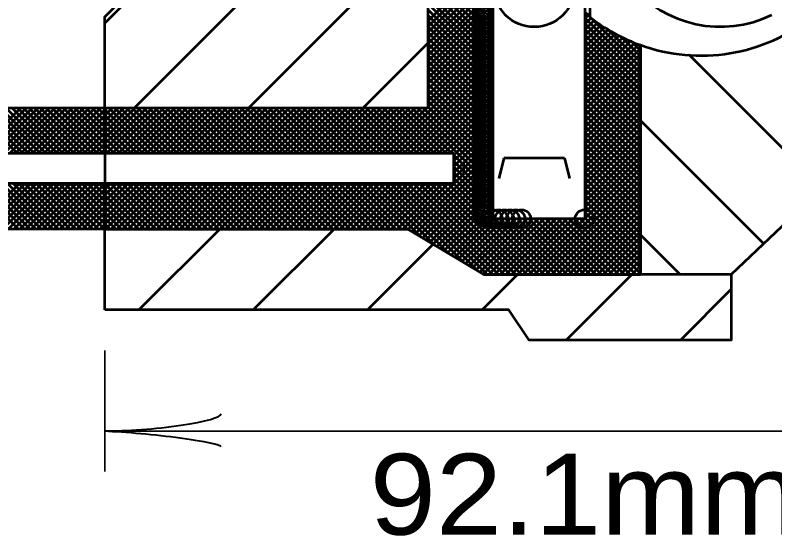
# Model space of a CAD drawing. Extents: x -32 to 824, y -6 to 538.
# Drawn here: x 144.51 to 167.06, y 179.61 to 195.06 of the extents above; entities that cross this region are included whole.
import ezdxf

# ---------------------------------------------------------------- set-up
doc = ezdxf.new("R2010")
doc.units = 0
doc.header["$LTSCALE"] = 1.1
doc.header["$PDMODE"] = 32
doc.header["$PDSIZE"] = 0.55
doc.layers.add('1', color=7, linetype='Continuous', lineweight=53)

msp = doc.modelspace()

# ---------------------------------------------------------------- linework, layer by layer
at = {"layer": '1'}
for p, q in [((161.565, 196.814), (161.565, 195.014)), ((158.415, 194.934), (156.765, 196.584)), ((156.765, 194.898), (158.415, 196.548)), ((158.415, 194.764), (156.765, 196.414)), ((156.765, 194.728), (158.415, 196.378)), ((158.415, 194.595), (156.765, 196.245)), ((156.765, 194.559), (158.415, 196.209)), ((158.415, 194.425), (156.765, 196.075)), ((156.765, 194.389), (158.415, 196.039)), ((158.415, 194.255), (156.765, 195.905)), ((156.765, 194.219), (158.415, 195.869)), ((158.415, 194.085), (156.765, 195.736)), ((147.165, 194.829), (147.951, 195.614)), ((148.045, 192.314), (151.345, 195.614)), ((151.439, 192.314), (154.739, 195.614)), ((156.765, 194.049), (158.415, 195.699)), ((158.415, 193.916), (156.765, 195.566)), ((156.765, 193.88), (158.415, 195.53)), ((158.415, 193.746), (156.765, 195.396)), ((156.765, 193.71), (158.415, 195.36)), ((158.415, 193.576), (156.765, 195.226)), ((156.765, 193.54), (158.415, 195.19)), ((158.415, 193.407), (156.765, 195.057)), ((163.065, 193.508), (161.415, 195.158)), ((161.415, 194.966), (161.565, 195.116)), ((156.765, 193.371), (158.415, 195.021)), ((158.415, 193.237), (156.765, 194.887)), ((156.765, 193.201), (158.415, 194.851)), ((163.065, 193.339), (161.415, 194.989)), ((161.415, 194.796), (161.605, 194.986)), ((161.415, 194.627), (161.704, 194.915)), ((161.415, 194.457), (161.803, 194.845)), ((163.065, 193.169), (161.415, 194.819)), ((158.415, 193.067), (156.765, 194.717)), ((156.765, 193.031), (158.415, 194.681)), ((161.415, 194.287), (161.903, 194.774)), ((161.415, 194.117), (162.002, 194.704)), ((163.065, 192.999), (161.415, 194.649)), ((161.415, 193.948), (162.109, 194.641)), ((163.065, 193.678), (162.095, 194.648)), ((158.415, 192.898), (156.765, 194.548)), ((156.765, 192.862), (158.415, 194.512)), ((158.415, 192.728), (156.765, 194.378)), ((161.415, 193.778), (162.217, 194.579)), ((161.415, 193.608), (162.326, 194.518)), ((163.065, 192.83), (161.415, 194.48)), ((161.415, 193.439), (162.434, 194.457)), ((161.415, 193.269), (162.546, 194.4)), ((163.065, 193.848), (162.485, 194.428)), ((154.833, 192.314), (156.765, 194.246)), ((156.765, 192.692), (158.415, 194.342)), ((158.415, 192.558), (156.765, 194.208)), ((156.765, 192.522), (158.415, 194.172)), ((161.415, 193.099), (162.665, 194.348)), ((163.065, 192.66), (161.415, 194.31)), ((161.415, 192.929), (162.783, 194.297)), ((161.415, 192.76), (162.901, 194.246)), ((161.415, 192.59), (163.02, 194.195)), ((163.065, 192.49), (161.415, 194.14)), ((163.065, 194.018), (162.789, 194.294)), ((163.065, 187.364), (163.065, 194.178)), ((158.415, 192.389), (156.765, 194.038)), ((156.765, 192.352), (158.415, 194.002)), ((161.415, 192.42), (163.065, 194.07)), ((163.065, 192.321), (161.415, 193.971)), ((155.547, 190.964), (158.415, 193.833)), ((158.415, 192.219), (156.765, 193.869)), ((158.415, 192.049), (156.765, 193.699)), ((161.415, 192.251), (163.065, 193.901)), ((163.065, 192.151), (161.415, 193.801)), ((161.415, 192.081), (163.065, 193.731)), ((168.468, 189.932), (164.519, 193.881)), ((155.717, 190.964), (158.415, 193.663)), ((155.886, 190.964), (158.415, 193.493)), ((158.415, 191.879), (156.765, 193.529)), ((163.065, 191.981), (161.415, 193.631)), ((161.415, 191.911), (163.065, 193.561)), ((163.065, 191.811), (161.415, 193.461)), ((156.056, 190.964), (158.415, 193.323)), ((158.415, 191.71), (156.765, 193.36)), ((161.415, 191.742), (163.065, 193.392)), ((163.065, 191.642), (161.415, 193.292)), ((156.226, 190.964), (158.415, 193.154)), ((158.415, 191.54), (156.765, 193.19)), ((158.415, 191.37), (156.765, 193.02)), ((161.415, 191.572), (163.065, 193.222)), ((163.065, 191.472), (161.415, 193.122)), ((161.415, 191.402), (163.065, 193.052)), ((156.395, 190.964), (158.415, 192.984)), ((156.565, 190.964), (158.415, 192.814)), ((158.415, 191.201), (156.765, 192.851)), ((163.065, 191.302), (161.415, 192.952)), ((161.415, 191.232), (163.065, 192.882)), ((156.735, 190.964), (158.415, 192.645)), ((158.415, 191.031), (156.765, 192.681)), ((163.065, 191.133), (161.415, 192.783)), ((161.415, 191.063), (163.065, 192.713)), ((163.065, 190.963), (161.415, 192.613)), ((158.415, 190.861), (156.765, 192.511)), ((158.415, 190.691), (156.765, 192.341)), ((156.905, 190.964), (158.415, 192.475)), ((161.415, 190.893), (163.065, 192.543)), ((163.065, 190.793), (161.415, 192.443)), ((161.415, 190.723), (163.065, 192.373)), ((144.566, 190.964), (143.216, 192.314)), ((143.328, 190.964), (144.678, 192.314)), ((144.736, 190.964), (143.386, 192.314)), ((143.498, 190.964), (144.848, 192.314)), ((144.906, 190.964), (143.556, 192.314)), ((143.668, 190.964), (145.018, 192.314)), ((145.075, 190.964), (143.725, 192.314)), ((143.837, 190.964), (145.187, 192.314)), ((145.245, 190.964), (143.895, 192.314)), ((144.007, 190.964), (145.357, 192.314)), ((145.415, 190.964), (144.065, 192.314)), ((144.177, 190.964), (145.527, 192.314)), ((145.585, 190.964), (144.234, 192.314)), ((144.346, 190.964), (145.696, 192.314)), ((145.754, 190.964), (144.404, 192.314)), ((144.516, 190.964), (145.866, 192.314)), ((145.924, 190.964), (144.574, 192.314)), ((144.686, 190.964), (146.036, 192.314)), ((146.094, 190.964), (144.744, 192.314)), ((144.855, 190.964), (146.205, 192.314)), ((146.263, 190.964), (144.913, 192.314)), ((145.025, 190.964), (146.375, 192.314)), ((146.433, 190.964), (145.083, 192.314)), ((145.195, 190.964), (146.545, 192.314)), ((146.603, 190.964), (145.253, 192.314)), ((145.365, 190.964), (146.715, 192.314)), ((146.772, 190.964), (145.422, 192.314)), ((145.534, 190.964), (146.884, 192.314)), ((146.942, 190.964), (145.592, 192.314)), ((145.704, 190.964), (147.054, 192.314)), ((147.112, 190.964), (145.762, 192.314)), ((145.874, 190.964), (147.224, 192.314)), ((147.281, 190.964), (145.931, 192.314)), ((146.043, 190.964), (147.393, 192.314)), ((147.451, 190.964), (146.101, 192.314)), ((146.213, 190.964), (147.563, 192.314)), ((147.621, 190.964), (146.271, 192.314)), ((146.383, 190.964), (147.733, 192.314)), ((147.791, 190.964), (146.441, 192.314)), ((146.553, 190.964), (147.903, 192.314)), ((147.96, 190.964), (146.61, 192.314)), ((146.722, 190.964), (148.072, 192.314)), ((148.13, 190.964), (146.78, 192.314)), ((146.892, 190.964), (148.242, 192.314)), ((148.3, 190.964), (146.95, 192.314)), ((147.062, 190.964), (148.412, 192.314)), ((148.47, 190.964), (147.12, 192.314)), ((147.165, 192.314), (147.165, 188.714)), ((147.231, 190.964), (148.581, 192.314)), ((148.639, 190.964), (147.289, 192.314)), ((147.401, 190.964), (148.751, 192.314)), ((148.809, 190.964), (147.459, 192.314)), ((147.571, 190.964), (148.921, 192.314)), ((148.979, 190.964), (147.629, 192.314)), ((147.74, 190.964), (149.09, 192.314)), ((149.148, 190.964), (147.798, 192.314)), ((147.91, 190.964), (149.26, 192.314)), ((149.318, 190.964), (147.968, 192.314)), ((148.08, 190.964), (149.43, 192.314)), ((149.488, 190.964), (148.138, 192.314)), ((148.25, 190.964), (149.6, 192.314)), ((149.657, 190.964), (148.307, 192.314)), ((148.419, 190.964), (149.769, 192.314)), ((149.827, 190.964), (148.477, 192.314)), ((148.589, 190.964), (149.939, 192.314)), ((149.997, 190.964), (148.647, 192.314)), ((148.759, 190.964), (150.109, 192.314)), ((150.167, 190.964), (148.817, 192.314)), ((148.928, 190.964), (150.278, 192.314)), ((150.336, 190.964), (148.986, 192.314)), ((149.098, 190.964), (150.448, 192.314)), ((150.506, 190.964), (149.156, 192.314)), ((149.268, 190.964), (150.618, 192.314)), ((150.676, 190.964), (149.326, 192.314)), ((149.437, 190.964), (150.787, 192.314)), ((150.845, 190.964), (149.495, 192.314)), ((149.607, 190.964), (150.957, 192.314)), ((151.015, 190.964), (149.665, 192.314)), ((149.777, 190.964), (151.127, 192.314)), ((151.185, 190.964), (149.835, 192.314)), ((149.947, 190.964), (151.297, 192.314)), ((151.355, 190.964), (150.005, 192.314)), ((150.116, 190.964), (151.466, 192.314)), ((151.524, 190.964), (150.174, 192.314)), ((150.286, 190.964), (151.636, 192.314)), ((151.694, 190.964), (150.344, 192.314)), ((150.456, 190.964), (151.806, 192.314)), ((151.864, 190.964), (150.514, 192.314)), ((150.625, 190.964), (151.975, 192.314)), ((152.033, 190.964), (150.683, 192.314)), ((150.795, 190.964), (152.145, 192.314)), ((152.203, 190.964), (150.853, 192.314)), ((150.965, 190.964), (152.315, 192.314)), ((152.373, 190.964), (151.023, 192.314)), ((151.135, 190.964), (152.484, 192.314)), ((152.542, 190.964), (151.192, 192.314)), ((151.304, 190.964), (152.654, 192.314)), ((152.712, 190.964), (151.362, 192.314)), ((151.474, 190.964), (152.824, 192.314)), ((152.882, 190.964), (151.532, 192.314)), ((151.644, 190.964), (152.994, 192.314)), ((153.052, 190.964), (151.702, 192.314)), ((151.813, 190.964), (153.163, 192.314)), ((153.221, 190.964), (151.871, 192.314)), ((151.983, 190.964), (153.333, 192.314)), ((153.391, 190.964), (152.041, 192.314)), ((152.153, 190.964), (153.503, 192.314)), ((153.561, 190.964), (152.211, 192.314)), ((152.322, 190.964), (153.672, 192.314)), ((153.73, 190.964), (152.38, 192.314)), ((152.492, 190.964), (153.842, 192.314)), ((153.9, 190.964), (152.55, 192.314)), ((152.662, 190.964), (154.012, 192.314)), ((154.07, 190.964), (152.72, 192.314)), ((152.832, 190.964), (154.182, 192.314)), ((154.24, 190.964), (152.889, 192.314)), ((153.001, 190.964), (154.351, 192.314)), ((154.409, 190.964), (153.059, 192.314)), ((153.171, 190.964), (154.521, 192.314)), ((154.579, 190.964), (153.229, 192.314)), ((153.341, 190.964), (154.691, 192.314)), ((154.749, 190.964), (153.399, 192.314)), ((153.51, 190.964), (154.86, 192.314)), ((154.918, 190.964), (153.568, 192.314)), ((153.68, 190.964), (155.03, 192.314)), ((155.088, 190.964), (153.738, 192.314)), ((153.85, 190.964), (155.2, 192.314)), ((155.258, 190.964), (153.908, 192.314)), ((154.019, 190.964), (155.37, 192.314)), ((155.427, 190.964), (154.077, 192.314)), ((154.189, 190.964), (155.539, 192.314)), ((155.597, 190.964), (154.247, 192.314)), ((154.359, 190.964), (155.709, 192.314)), ((155.767, 190.964), (154.417, 192.314)), ((154.529, 190.964), (155.879, 192.314)), ((155.936, 190.964), (154.587, 192.314)), ((154.698, 190.964), (156.048, 192.314)), ((156.106, 190.964), (154.756, 192.314)), ((154.868, 190.964), (156.218, 192.314)), ((156.276, 190.964), (154.926, 192.314)), ((155.038, 190.964), (156.388, 192.314)), ((156.446, 190.964), (155.096, 192.314)), ((155.207, 190.964), (156.557, 192.314)), ((156.615, 190.964), (155.265, 192.314)), ((155.377, 190.964), (156.727, 192.314)), ((156.785, 190.964), (155.435, 192.314)), ((156.955, 190.964), (155.605, 192.314)), ((157.125, 190.964), (155.775, 192.314)), ((157.294, 190.964), (155.944, 192.314)), ((157.464, 190.964), (156.114, 192.314)), ((158.415, 190.182), (156.284, 192.314)), ((158.415, 190.352), (156.453, 192.314)), ((158.415, 190.522), (156.623, 192.314)), ((157.074, 190.964), (158.415, 192.305)), ((157.244, 190.964), (158.415, 192.136)), ((163.065, 190.623), (161.415, 192.273)), ((161.415, 190.554), (163.065, 192.204)), ((157.414, 190.964), (158.415, 191.966)), ((163.065, 190.454), (161.415, 192.104)), ((161.415, 190.384), (163.065, 192.034)), ((163.065, 190.284), (161.415, 191.934)), ((166.728, 188.278), (163.065, 191.94)), ((157.515, 190.896), (158.415, 191.796)), ((161.415, 190.214), (163.065, 191.864)), ((163.065, 190.114), (161.415, 191.764)), ((161.415, 190.044), (163.065, 191.694)), ((157.515, 190.727), (158.415, 191.627)), ((157.515, 190.557), (158.415, 191.457)), ((163.065, 189.945), (161.415, 191.595)), ((161.415, 189.875), (163.065, 191.525)), ((157.515, 190.387), (158.415, 191.287)), ((163.065, 189.775), (161.415, 191.425)), ((161.415, 189.705), (163.065, 191.355)), ((163.065, 189.605), (161.415, 191.255)), ((157.515, 190.217), (158.415, 191.117)), ((161.415, 189.535), (163.065, 191.185)), ((163.065, 189.436), (161.415, 191.085)), ((161.415, 189.366), (163.065, 191.016)), ((156.176, 188.708), (158.415, 190.948)), ((156.282, 188.644), (158.415, 190.778)), ((158.415, 190.013), (157.515, 190.913)), ((159.015, 190.814), (158.865, 190.214)), ((160.815, 190.814), (159.015, 190.814)), ((160.815, 190.814), (160.965, 190.214)), ((163.065, 189.266), (161.415, 190.916)), ((161.415, 189.196), (163.065, 190.846)), ((156.388, 188.581), (158.415, 190.608)), ((158.415, 189.843), (157.515, 190.743)), ((158.415, 189.673), (157.515, 190.573)), ((157.815, 190.664), (157.815, 190.364)), ((163.065, 189.096), (161.415, 190.746)), ((161.415, 189.026), (163.065, 190.676)), ((163.065, 188.926), (161.415, 190.576)), ((156.494, 188.517), (158.415, 190.439)), ((158.415, 189.504), (157.515, 190.404)), ((159.923, 187.364), (163.065, 190.507)), ((160.093, 187.364), (163.065, 190.337)), ((163.065, 188.757), (161.415, 190.407)), ((156.6, 188.453), (158.415, 190.269)), ((156.706, 188.39), (158.415, 190.099)), ((158.415, 189.334), (157.515, 190.234)), ((160.262, 187.364), (163.065, 190.167)), ((163.065, 188.587), (161.415, 190.237)), ((144.61, 188.714), (143.26, 190.064)), ((143.284, 188.714), (144.634, 190.064)), ((144.78, 188.714), (143.43, 190.064)), ((143.454, 188.714), (144.804, 190.064)), ((144.95, 188.714), (143.6, 190.064)), ((143.624, 188.714), (144.974, 190.064)), ((145.119, 188.714), (143.769, 190.064)), ((143.793, 188.714), (145.143, 190.064)), ((145.289, 188.714), (143.939, 190.064)), ((143.963, 188.714), (145.313, 190.064)), ((145.459, 188.714), (144.109, 190.064)), ((144.133, 188.714), (145.483, 190.064)), ((145.628, 188.714), (144.278, 190.064)), ((144.303, 188.714), (145.653, 190.064)), ((145.798, 188.714), (144.448, 190.064)), ((144.472, 188.714), (145.822, 190.064)), ((145.968, 188.714), (144.618, 190.064)), ((144.642, 188.714), (145.992, 190.064)), ((146.137, 188.714), (144.787, 190.064)), ((144.812, 188.714), (146.162, 190.064)), ((146.307, 188.714), (144.957, 190.064)), ((144.981, 188.714), (146.331, 190.064)), ((146.477, 188.714), (145.127, 190.064)), ((145.151, 188.714), (146.501, 190.064)), ((146.647, 188.714), (145.297, 190.064)), ((145.321, 188.714), (146.671, 190.064)), ((146.816, 188.714), (145.466, 190.064)), ((145.49, 188.714), (146.84, 190.064)), ((146.986, 188.714), (145.636, 190.064)), ((145.66, 188.714), (147.01, 190.064)), ((147.156, 188.714), (145.806, 190.064)), ((145.83, 188.714), (147.18, 190.064)), ((147.325, 188.714), (145.975, 190.064)), ((146, 188.714), (147.35, 190.064)), ((147.495, 188.714), (146.145, 190.064)), ((146.169, 188.714), (147.519, 190.064)), ((147.665, 188.714), (146.315, 190.064)), ((146.339, 188.714), (147.689, 190.064)), ((147.835, 188.714), (146.484, 190.064)), ((146.509, 188.714), (147.859, 190.064)), ((148.004, 188.714), (146.654, 190.064)), ((146.678, 188.714), (148.028, 190.064)), ((148.174, 188.714), (146.824, 190.064)), ((146.848, 188.714), (148.198, 190.064)), ((148.344, 188.714), (146.994, 190.064)), ((147.018, 188.714), (148.368, 190.064)), ((148.513, 188.714), (147.163, 190.064)), ((147.187, 188.714), (148.537, 190.064)), ((148.683, 188.714), (147.333, 190.064)), ((147.357, 188.714), (148.707, 190.064)), ((148.853, 188.714), (147.503, 190.064)), ((147.527, 188.714), (148.877, 190.064)), ((149.022, 188.714), (147.672, 190.064)), ((147.697, 188.714), (149.047, 190.064)), ((149.192, 188.714), (147.842, 190.064)), ((147.866, 188.714), (149.216, 190.064)), ((149.362, 188.714), (148.012, 190.064)), ((148.036, 188.714), (149.386, 190.064)), ((149.531, 188.714), (148.181, 190.064)), ((148.206, 188.714), (149.556, 190.064)), ((149.701, 188.714), (148.351, 190.064)), ((148.375, 188.714), (149.725, 190.064)), ((149.871, 188.714), (148.521, 190.064)), ((148.545, 188.714), (149.895, 190.064)), ((150.041, 188.714), (148.691, 190.064)), ((148.715, 188.714), (150.065, 190.064)), ((150.21, 188.714), (148.86, 190.064)), ((148.885, 188.714), (150.234, 190.064)), ((150.38, 188.714), (149.03, 190.064)), ((149.054, 188.714), (150.404, 190.064)), ((150.55, 188.714), (149.2, 190.064)), ((149.224, 188.714), (150.574, 190.064)), ((150.72, 188.714), (149.37, 190.064)), ((149.394, 188.714), (150.744, 190.064)), ((150.889, 188.714), (149.539, 190.064)), ((149.563, 188.714), (150.913, 190.064)), ((151.059, 188.714), (149.709, 190.064)), ((149.733, 188.714), (151.083, 190.064)), ((151.229, 188.714), (149.879, 190.064)), ((149.903, 188.714), (151.253, 190.064)), ((151.398, 188.714), (150.048, 190.064)), ((150.072, 188.714), (151.422, 190.064)), ((151.568, 188.714), (150.218, 190.064)), ((150.242, 188.714), (151.592, 190.064)), ((151.738, 188.714), (150.388, 190.064)), ((150.412, 188.714), (151.762, 190.064)), ((151.907, 188.714), (150.557, 190.064)), ((150.582, 188.714), (151.932, 190.064)), ((152.077, 188.714), (150.727, 190.064)), ((150.751, 188.714), (152.101, 190.064)), ((152.247, 188.714), (150.897, 190.064)), ((150.921, 188.714), (152.271, 190.064)), ((152.417, 188.714), (151.067, 190.064)), ((151.091, 188.714), (152.441, 190.064)), ((152.586, 188.714), (151.236, 190.064)), ((151.26, 188.714), (152.61, 190.064)), ((152.756, 188.714), (151.406, 190.064)), ((151.43, 188.714), (152.78, 190.064)), ((152.926, 188.714), (151.576, 190.064)), ((151.6, 188.714), (152.95, 190.064)), ((153.095, 188.714), (151.745, 190.064)), ((151.769, 188.714), (153.12, 190.064)), ((153.265, 188.714), (151.915, 190.064)), ((151.939, 188.714), (153.289, 190.064)), ((153.435, 188.714), (152.085, 190.064)), ((152.109, 188.714), (153.459, 190.064)), ((153.605, 188.714), (152.255, 190.064)), ((152.279, 188.714), (153.629, 190.064)), ((153.774, 188.714), (152.424, 190.064)), ((152.448, 188.714), (153.798, 190.064)), ((153.944, 188.714), (152.594, 190.064)), ((152.618, 188.714), (153.968, 190.064)), ((154.114, 188.714), (152.764, 190.064)), ((152.788, 188.714), (154.138, 190.064)), ((154.283, 188.714), (152.933, 190.064)), ((152.957, 188.714), (154.307, 190.064)), ((154.453, 188.714), (153.103, 190.064)), ((153.127, 188.714), (154.477, 190.064)), ((154.623, 188.714), (153.273, 190.064)), ((153.297, 188.714), (154.647, 190.064)), ((154.792, 188.714), (153.442, 190.064)), ((153.467, 188.714), (154.817, 190.064)), ((154.962, 188.714), (153.612, 190.064)), ((153.636, 188.714), (154.986, 190.064)), ((155.132, 188.714), (153.782, 190.064)), ((153.806, 188.714), (155.156, 190.064)), ((155.302, 188.714), (153.952, 190.064)), ((153.976, 188.714), (155.326, 190.064)), ((155.471, 188.714), (154.121, 190.064)), ((154.145, 188.714), (155.495, 190.064)), ((155.641, 188.714), (154.291, 190.064)), ((154.315, 188.714), (155.665, 190.064)), ((155.811, 188.714), (154.461, 190.064)), ((154.485, 188.714), (155.835, 190.064)), ((155.98, 188.714), (154.63, 190.064)), ((154.655, 188.714), (156.005, 190.064)), ((156.15, 188.714), (154.8, 190.064)), ((154.824, 188.714), (156.174, 190.064)), ((156.551, 188.483), (154.97, 190.064)), ((154.994, 188.714), (156.344, 190.064)), ((156.976, 188.228), (155.139, 190.064)), ((155.164, 188.714), (156.514, 190.064)), ((157.4, 187.973), (155.309, 190.064)), ((155.333, 188.714), (156.683, 190.064)), ((157.824, 187.719), (155.479, 190.064)), ((155.503, 188.714), (156.853, 190.064)), ((158.248, 187.464), (155.649, 190.064)), ((155.673, 188.714), (157.023, 190.064)), ((158.518, 187.364), (155.818, 190.064)), ((155.842, 188.714), (157.192, 190.064)), ((158.688, 187.364), (155.988, 190.064)), ((156.012, 188.714), (157.362, 190.064)), ((158.858, 187.364), (156.158, 190.064)), ((159.027, 187.364), (156.327, 190.064)), ((159.197, 187.364), (156.497, 190.064)), ((159.367, 187.364), (156.667, 190.064)), ((156.812, 188.326), (158.415, 189.929)), ((159.537, 187.364), (156.837, 190.064)), ((159.706, 187.364), (157.006, 190.064)), ((159.876, 187.364), (157.176, 190.064)), ((160.046, 187.364), (157.346, 190.064)), ((158.415, 189.164), (157.515, 190.064)), ((160.432, 187.364), (163.065, 189.997)), ((163.065, 188.417), (161.415, 190.067)), ((163.065, 188.248), (161.415, 189.898)), ((156.918, 188.263), (158.415, 189.76)), ((160.602, 187.364), (163.065, 189.828)), ((160.772, 187.364), (163.065, 189.658)), ((163.065, 188.078), (161.415, 189.728)), ((157.024, 188.199), (158.415, 189.59)), ((157.13, 188.135), (158.415, 189.42)), ((160.941, 187.364), (163.065, 189.488)), ((163.065, 187.908), (161.415, 189.558)), ((157.236, 188.072), (158.415, 189.251)), ((161.111, 187.364), (163.065, 189.319)), ((163.065, 187.739), (161.415, 189.389)), ((163.065, 187.569), (161.415, 189.219)), ((157.342, 188.008), (158.415, 189.081)), ((157.448, 187.944), (158.518, 189.014)), ((157.555, 187.881), (158.688, 189.014)), ((157.661, 187.817), (158.858, 189.014)), ((157.767, 187.753), (159.027, 189.014)), ((157.873, 187.69), (159.197, 189.014)), ((157.979, 187.626), (159.367, 189.014)), ((158.085, 187.562), (159.537, 189.014)), ((158.191, 187.499), (159.706, 189.014)), ((158.297, 187.435), (159.876, 189.014)), ((158.403, 187.371), (160.046, 189.014)), ((158.565, 187.364), (160.215, 189.014)), ((160.215, 187.364), (158.565, 189.014)), ((158.735, 187.364), (160.385, 189.014)), ((160.385, 187.364), (158.735, 189.014)), ((158.905, 187.364), (160.555, 189.014)), ((160.555, 187.364), (158.905, 189.014)), ((159.075, 187.364), (160.725, 189.014)), ((160.725, 187.364), (159.075, 189.014)), ((159.244, 187.364), (160.894, 189.014)), ((160.894, 187.364), (159.244, 189.014)), ((159.414, 187.364), (161.064, 189.014)), ((161.064, 187.364), (159.414, 189.014)), ((159.584, 187.364), (161.234, 189.014)), ((161.234, 187.364), (159.584, 189.014)), ((159.753, 187.364), (161.403, 189.014)), ((161.403, 187.364), (159.753, 189.014)), ((161.573, 187.364), (159.923, 189.014)), ((161.743, 187.364), (160.093, 189.014)), ((161.912, 187.364), (160.262, 189.014)), ((162.082, 187.364), (160.432, 189.014)), ((162.252, 187.364), (160.602, 189.014)), ((162.422, 187.364), (160.772, 189.014)), ((162.591, 187.364), (160.941, 189.014)), ((162.761, 187.364), (161.111, 189.014)), ((161.281, 187.364), (163.065, 189.149)), ((162.931, 187.364), (161.281, 189.014)), ((163.065, 187.399), (161.415, 189.049)), ((161.45, 187.364), (163.065, 188.979)), ((161.62, 187.364), (163.065, 188.809)), ((147.165, 188.691), (147.189, 188.714)), ((148.183, 186.314), (150.583, 188.714)), ((151.577, 186.314), (153.977, 188.714)), ((161.79, 187.364), (163.065, 188.64)), ((164.247, 187.364), (163.065, 188.546)), ((161.96, 187.364), (163.065, 188.47)), ((162.129, 187.364), (163.065, 188.3)), ((154.971, 186.314), (156.919, 188.262)), ((162.299, 187.364), (163.065, 188.131)), ((162.469, 187.364), (163.065, 187.961)), ((162.638, 187.364), (163.065, 187.791)), ((162.808, 187.364), (163.065, 187.621)), ((162.978, 187.364), (163.065, 187.452)), ((158.365, 186.314), (159.415, 187.364)), ((160.859, 185.414), (162.809, 187.364)), ((164.253, 185.414), (165.765, 186.926))]:
    msp.add_line(p, q, dxfattribs=at)
at = {"layer": '1', "lineweight": 35}
for p, q in [((147.165, 185.114), (147.165, 181.514)), ((147.165, 182.714), (174.765, 182.714))]:
    msp.add_line(p, q, dxfattribs=at)
at = {"layer": '1'}
for points in [[(158.415, 189.014), (158.415, 202.814), (161.415, 202.814), (161.415, 189.014)], [(158.415, 202.814), (161.415, 202.814), (161.415, 189.014), (158.415, 189.014)], [(136.365, 190.064), (136.365, 190.964), (157.515, 190.964), (157.515, 190.064)]]:
    msp.add_lwpolyline(points, close=True, dxfattribs=at)
for points in [[(163.065, 194.178), (163.065, 187.364), (158.415, 187.364), (156.165, 188.714), (147.165, 188.714), (135.765, 188.714), (135.765, 189.764), (135.765, 191.264), (135.765, 192.314), (147.165, 192.314), (156.765, 192.314), (156.765, 199.514), (147.165, 199.514)], [(147.165, 192.314), (156.765, 192.314), (156.765, 199.514), (147.165, 199.514)], [(147.165, 192.314), (147.165, 195.014), (147.765, 195.614)], [(168.165, 195.014), (174.765, 195.014), (174.765, 193.214), (168.765, 193.214), (168.765, 190.214), (165.765, 187.364), (163.065, 187.364)], [(163.065, 194.178), (163.065, 187.364), (158.415, 187.364), (156.165, 188.714), (147.165, 188.714)], [(147.165, 186.314), (147.165, 188.714), (156.165, 188.714), (158.415, 187.364), (163.065, 187.364)], [(165.765, 187.364), (165.765, 185.414), (159.765, 185.414), (159.165, 186.314), (147.165, 186.314)]]:
    msp.add_lwpolyline(points, dxfattribs=at)
msp.add_circle((159.915, 195.914), 1.2, dxfattribs=at)
for centre, radius, start, end in [((165.444, 198.22), 3.498, 220.0303, 295.7802), ((164.865, 199.171), 5.307, 231.552, 250.174), ((164.865, 199.171), 5.307, 250.174, 308.448)]:
    msp.add_arc(centre, radius, start, end, dxfattribs=at)
at = {"layer": '1', "lineweight": 40}
for centre, major_axis, ratio, start_param, end_param in [((148.475, 183.046), (-2.143, -0.187), 0.122415, 0.896353, 3.141593), ((148.475, 183.046), (-2.143, -0.187), 0.122415, 0.896353, 3.141593), ((148.51, 182.46), (-2.108, 0.211), 0.07063, 3.140715, 5.41811), ((148.51, 182.46), (-2.108, 0.211), 0.07063, 3.140715, 5.41811)]:
    msp.add_ellipse(centre, major_axis=major_axis, ratio=ratio, start_param=start_param, end_param=end_param, dxfattribs=at)
at = {"layer": '1'}
for p in [(158.415, 195.273), (158.415, 195.19), (158.415, 195.104), (158.415, 195.021), (158.415, 194.934), (158.415, 194.851), (158.415, 194.764), (158.415, 194.681), (158.415, 194.595), (158.415, 194.512), (158.415, 194.425), (158.415, 194.342), (158.415, 194.255), (158.415, 194.172), (158.415, 194.085), (158.415, 194.002), (158.415, 193.916), (158.415, 193.833), (158.415, 193.746), (158.415, 193.663), (158.415, 193.576), (158.415, 193.493), (158.415, 193.407), (158.415, 193.323), (158.415, 193.237), (158.415, 193.154), (158.415, 193.067), (158.415, 192.984), (158.415, 192.898), (158.415, 192.814), (158.415, 192.728), (158.415, 192.645), (158.415, 192.558), (158.415, 192.475), (158.415, 192.389), (158.415, 192.305), (158.415, 192.219), (158.415, 192.136), (158.415, 192.049), (158.415, 191.966), (158.415, 191.879), (158.415, 191.796), (158.415, 191.71), (158.415, 191.627), (158.415, 191.54), (158.415, 191.457), (158.415, 191.37), (158.415, 191.287), (158.415, 191.201), (158.415, 191.117), (158.415, 191.031), (158.415, 190.948), (158.415, 190.861), (158.415, 190.778), (158.415, 190.691), (158.415, 190.608), (158.415, 190.522), (158.415, 190.439), (158.415, 190.352), (158.415, 190.269), (158.415, 190.182), (158.415, 190.099), (158.415, 190.013), (158.415, 189.929), (158.415, 189.843), (158.415, 189.76), (158.415, 189.673), (158.415, 189.59), (158.415, 189.504), (158.415, 189.42), (158.415, 189.334), (158.415, 189.251), (158.415, 189.164), (158.415, 189.081), (158.688, 189.014), (158.858, 189.014), (159.027, 189.014), (159.197, 189.014), (159.367, 189.014), (159.537, 189.014), (161.403, 189.014)]:
    msp.add_point(p, dxfattribs=at)

# ---------------------------------------------------------------- texts
at = {"layer": '1', "width": 1.1}
msp.add_text('92.1mm', height=2.4, dxfattribs=at).set_placement((155.033, 179.643))

doc.saveas('drawing.dxf')
